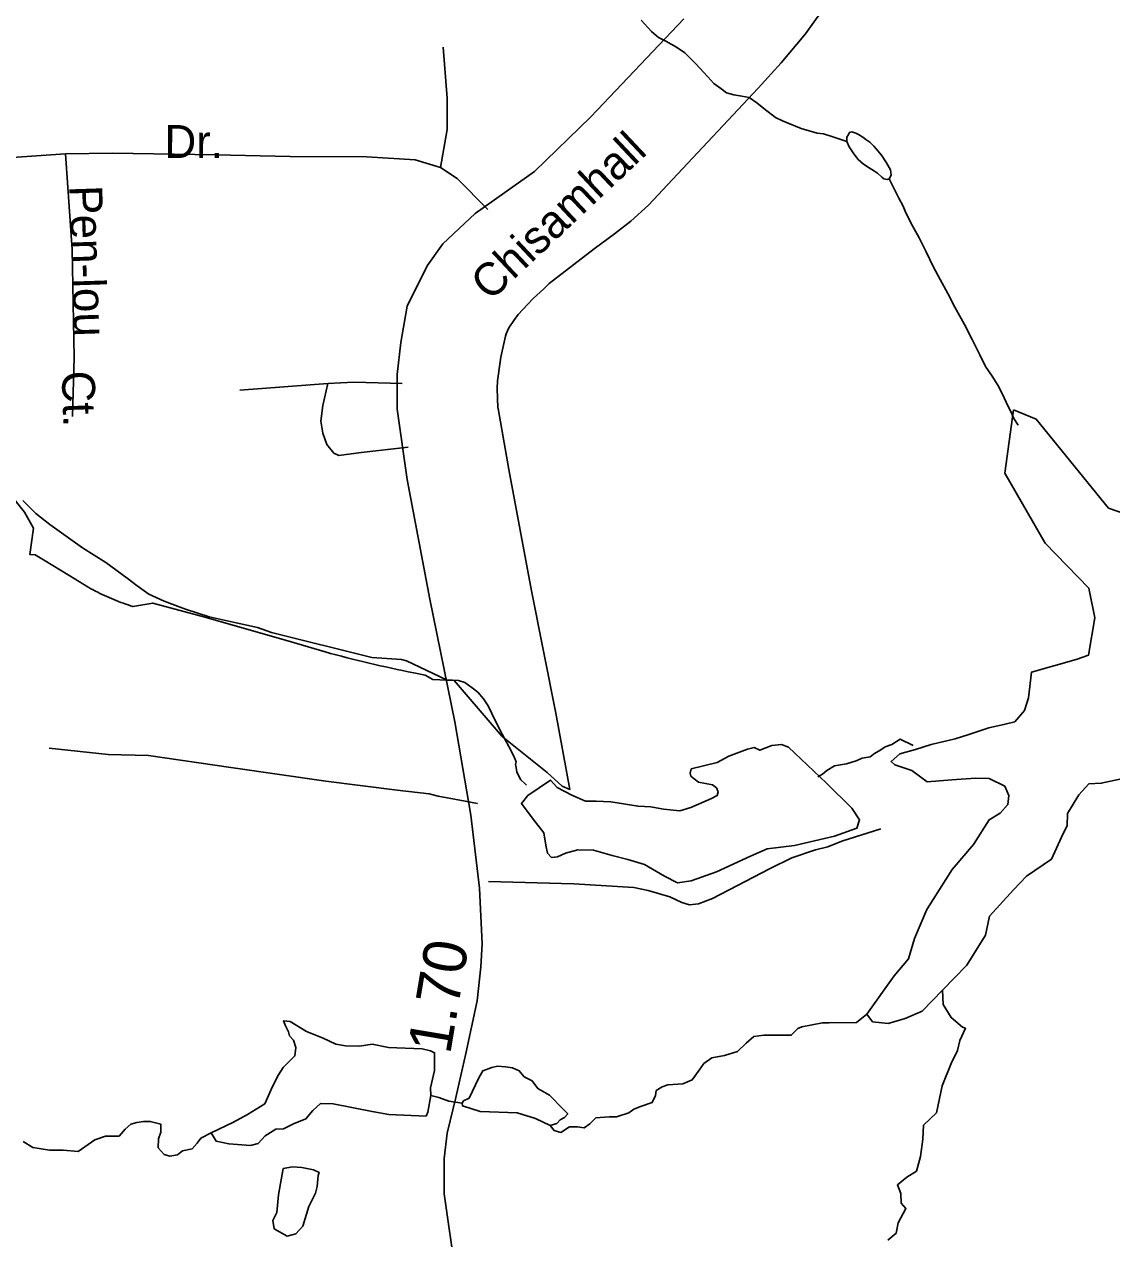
# Model space of a CAD drawing. Extents: x 2082433 to 2279600, y 546599 to 755198.
# Drawn here: x 2095833 to 2098975, y 639289 to 642798 of the extents above; entities that cross this region are included whole.
import ezdxf

# ---------------------------------------------------------------- set-up
doc = ezdxf.new("R2010")
doc.units = 0
for name, color, linetype in [('Exist Boundary Political Fire Districts', 7, 'Continuous'), ('Exist Hydrographic Creek Single Shore', 7, 'Continuous'), ('Exist Hydrographic Lake Shore', 7, 'Continuous'), ('Exist Hydrographic Pond Over 1500 Sq Ft', 7, 'Continuous'), ('Exist Road Non-System Type 51', 7, 'Continuous'), ('Exist Road Non-System Type 51 Label', 7, 'Continuous'), ('Exist Road Secondary Mileage Hundredths English Label', 7, 'Continuous'), ('Exist Road Secondary Type 51 Attributed', 7, 'Continuous'), ('Exist Road Secondary Type 51 Label', 7, 'Continuous')]:
    doc.layers.add(name, color=color, linetype=linetype)

msp = doc.modelspace()

# ---------------------------------------------------------------- linework, layer by layer
at = {"layer": 'Exist Boundary Political Fire Districts'}
for points in [[(2098155.5, 642861.7), (2098090.5, 642770.9), (2098020.5, 642686.3), (2097953.3, 642613.5), (2097706, 642349.4), (2097636.3, 642275.7), (2097586, 642229.6), (2097538.3, 642192.8), (2097480, 642149.7), (2097350, 642048.7), (2097335, 642034.9), (2097302.4, 642004.8), (2097260.4, 641959.8), (2097247.5, 641942.3), (2097232.9, 641921), (2097225.1, 641903.7), (2097223.7, 641897.2), (2097209.6, 641836.1), (2097200.7, 641768.2), (2097199.7, 641745.8), (2097201.6, 641689.9), (2097201.8, 641688.2), (2097232.7, 641511.5), (2097299, 641161.4), (2097369.3, 640807.7), (2097409.7, 640587.4), (2097387.5, 640596.3), (2097343.7, 640635.9), (2097214.1, 640740.5), (2097075.2, 640902.1), (2097013.7, 640904.7), (2096990.8, 640917.1), (2096958.4, 640924.3), (2096942.2, 640927.5), (2096926.2, 640930.8), (2096910, 640934.1), (2096894, 640937.6), (2096877.8, 640941.1), (2096861.6, 640944.6), (2096845.6, 640948.3), (2096829.6, 640952.1), (2096813.6, 640955.9), (2096797.4, 640959.7), (2096781.4, 640963.7), (2096765.6, 640967.7), (2096749.6, 640971.9), (2096733.6, 640976), (2096717.8, 640980.3), (2096701.8, 640984.6), (2096604, 641013.4), (2096358.6, 641083.8), (2096204, 641125.7), (2096146.8, 641115.7), (2096139.8, 641117.9), (2096132.8, 641120.2), (2096125.9, 641122.6), (2096119.1, 641125.1), (2096112.1, 641127.6), (2096105.3, 641130.2), (2096098.4, 641132.9), (2096091.6, 641135.6), (2096084.8, 641138.5), (2096078.1, 641141.4), (2096071.3, 641144.4), (2096064.7, 641147.4), (2096058.2, 641150.5), (2096051.4, 641153.7), (2096044.9, 641157), (2096038.3, 641160.4), (2096031.9, 641163.8), (2096025.4, 641167.3), (2096019, 641170.8), (2096012.7, 641174.4), (2096006.3, 641178.1), (2096000, 641181.9), (2095993.8, 641185.8), (2095987.4, 641189.7)], [(2095987.4, 641189.7), (2095981.3, 641193.6), (2095892.9, 641247.9), (2095864.6, 641265.2), (2095849, 641266), (2095859.3, 641342.1), (2095833.4, 641388.1), (2095809.9, 641417.3), (2095796.3, 641436.4), (2095719, 641489.7), (2095621.6, 641631.3), (2095543.7, 641668.5), (2095450, 641711.7), (2095302, 641847.1), (2095229.6, 641871.3), (2095175.4, 641897.6), (2095148, 641908), (2095048.9, 641984.4), (2095000.1, 642023.6), (2095005, 642083.8), (2092567, 642644)]]:
    msp.add_lwpolyline(points, dxfattribs=at)
at = {"layer": 'Exist Hydrographic Creek Single Shore'}
for points in [[(2097615.1, 642809.7), (2097645.1, 642777.6), (2097665.6, 642759.9), (2097687.1, 642749.7), (2097717.9, 642732.1), (2097741.5, 642715.9), (2097773.7, 642684.3), (2097807.7, 642646.3), (2097825.7, 642626.6), (2097845.8, 642612.5), (2097861.6, 642600.4), (2097883.6, 642594.6), (2097905.9, 642590.5), (2097927.8, 642586.7), (2097949.8, 642570.8), (2097969.7, 642554.8), (2098004.1, 642529), (2098024, 642519), (2098078.2, 642497), (2098123.9, 642483.2), (2098142.3, 642481.2), (2098166.1, 642473.6), (2098210.2, 642459.6)], [(2098332.4, 642351.9), (2098338.4, 642361.9), (2098336.3, 642378), (2098324.4, 642398.1), (2098310.3, 642420.1), (2098294.5, 642437.9), (2098288.1, 642445.8), (2098276, 642457.8), (2098264.3, 642465.6), (2098256.3, 642471.7), (2098244, 642479.6), (2098236.2, 642483.6), (2098224.1, 642487.5), (2098217.8, 642485.6), (2098214.3, 642479.7), (2098210, 642471.8), (2098210.2, 642459.6)], [(2098210.2, 642459.6), (2098216.4, 642443.7), (2098230.5, 642423.7), (2098242.2, 642407.7), (2098258.2, 642393.9), (2098274.4, 642383.8), (2098290.2, 642374.1), (2098298.6, 642367.9), (2098310.7, 642356), (2098316.6, 642351.8), (2098326.7, 642349.9), (2098332.4, 642351.9)], [(2098332.4, 642351.9), (2098360.5, 642296.1), (2098372.8, 642272.3), (2098378.8, 642258), (2098395, 642224.4), (2098419.2, 642180.6), (2098439, 642140.2), (2098459.3, 642098.6), (2098479.4, 642060.7), (2098501.6, 642020.4), (2098521.5, 641981), (2098549.6, 641930.9), (2098572.1, 641886.9), (2098594.1, 641843), (2098610.1, 641809), (2098630.2, 641781.2), (2098646.6, 641755.1), (2098660.1, 641729.2), (2098674.9, 641695.3), (2098684.5, 641677.2), (2098692.7, 641659.4), (2098704.6, 641639.3)], [(2095828.3, 641422.3), (2095866.1, 641384.5), (2095906.2, 641352.5), (2095954.2, 641318.9), (2096000.6, 641285.1), (2096068.2, 641243.2), (2096130.4, 641197.3), (2096158.7, 641175.6), (2096192.9, 641151.7), (2096236.8, 641131.7), (2096299.1, 641108.1), (2096366.8, 641086.1), (2096445.1, 641068.5), (2096507, 641054.7), (2096547.2, 641040.9), (2096837, 640968.9), (2096923.2, 640962.4), (2096936.9, 640958.6), (2097053.1, 640904.2), (2097087.3, 640902.3), (2097105.4, 640896.7), (2097127.5, 640880.8), (2097143.3, 640868.7), (2097159.5, 640848.8), (2097173.7, 640828.8), (2097183.7, 640807), (2097197.7, 640778.9), (2097214.1, 640746.9), (2097240.1, 640699.1), (2097249.7, 640679), (2097254.3, 640666.9), (2097252, 640659.2), (2097254, 640651.1), (2097256.1, 640637.1), (2097268, 640615), (2097280.1, 640603.4), (2097284.2, 640599.2)], [(2098125.9, 640623.8), (2098139.7, 640631.8), (2098151.6, 640642.2), (2098173.9, 640655.9), (2098209.3, 640661), (2098236.4, 640669.8), (2098254.2, 640677.6), (2098277, 640681), (2098289.3, 640690.8), (2098307.7, 640702), (2098320.5, 640710.7), (2098340, 640717.4), (2098363.6, 640732.6), (2098401.9, 640714.3)], [(2098327.9, 639284.8), (2098352.1, 639305.1), (2098357.9, 639334.8), (2098380.4, 639376.8), (2098367.1, 639392.2), (2098366.1, 639419.8), (2098355.8, 639444.4), (2098383.5, 639466.9), (2098411.2, 639484.4), (2098422.4, 639526.4), (2098429.9, 639577), (2098431.6, 639617), (2098468.5, 639652.4), (2098484.9, 639731.3), (2098511.6, 639795.8), (2098530, 639832.7), (2098536.2, 639861.4), (2098552.6, 639897.3), (2098544.4, 639900.3), (2098511.6, 639928), (2098488, 639965.9), (2098486, 640006.9)], [(2097352.3, 639616.5), (2097363.6, 639602.2), (2097383.1, 639596), (2097408.7, 639612.4), (2097431.2, 639612.4), (2097450.7, 639609.4), (2097467.1, 639620.6), (2097484.5, 639638), (2097523.4, 639641.1), (2097543.9, 639641.1), (2097579.8, 639652.4), (2097594.1, 639663.7), (2097616.6, 639671.9), (2097647.4, 639683.1), (2097656.6, 639702.6), (2097658.7, 639716.9), (2097676.1, 639728.2), (2097692.5, 639733.3), (2097735.5, 639736.4), (2097763.2, 639747.7), (2097782.6, 639776.4), (2097797, 639795.8), (2097819.5, 639812.2), (2097856.4, 639818.4), (2097894.3, 639829.6), (2097918.9, 639854.2), (2097941.4, 639873.7), (2097970.1, 639876.8), (2097986.5, 639876.8), (2098049, 639876.8), (2098068.5, 639896.2), (2098079.7, 639901.3), (2098139.2, 639912.6), (2098158.6, 639912.6), (2098237.5, 639913.6), (2098268, 639938.3)], [(2097008.1, 639702.6), (2097030.6, 639697.5), (2097059.3, 639686.2), (2097098.2, 639681.1)], [(2095829.9, 639570.4), (2095857.5, 639553), (2095905.7, 639544.8), (2095945.6, 639544.8), (2095988.7, 639540.7), (2096036.8, 639574.5), (2096067.6, 639585.8), (2096106.5, 639585.8), (2096123.9, 639605.3), (2096140.3, 639619.6), (2096157.7, 639624.7), (2096177.2, 639627.8), (2096196.6, 639627.8), (2096227.4, 639619.6), (2096227.4, 639597.1), (2096220.2, 639577.6), (2096219.2, 639552), (2096236.6, 639532.5), (2096253, 639527.4), (2096275.5, 639531.5), (2096289.9, 639542.8), (2096317.5, 639548.9), (2096331.9, 639565.3), (2096343.1, 639579.6), (2096372.9, 639595)]]:
    msp.add_lwpolyline(points, dxfattribs=at)
at = {"layer": 'Exist Hydrographic Lake Shore'}
for points in [[(2098268, 639938.3), (2098346.6, 640048.9), (2098387.6, 640098.1), (2098405, 640156.5), (2098440.9, 640240.5), (2098514.6, 640356.2), (2098576.1, 640428), (2098621.2, 640499.7), (2098653, 640519.1), (2098675.5, 640543.7), (2098677.5, 640569.3), (2098666.3, 640597), (2098620.7, 640619), (2098581.8, 640620.1), (2098513.6, 640614.9), (2098441.9, 640609.3), (2098397.9, 640641.6), (2098348.7, 640658.5), (2098337.9, 640668.2), (2098362.5, 640690.2), (2098408.1, 640702.5), (2098453.2, 640716.9), (2098522.8, 640733.3), (2098562.8, 640745.6), (2098620.2, 640765), (2098667.3, 640776.3), (2098695, 640782.4), (2098723.7, 640815.2), (2098734.9, 640852.1), (2098743.1, 640925.7), (2098872.7, 640962.8), (2098908.1, 640975.1), (2098926.2, 641082.7), (2098909.2, 641168.4), (2098783.1, 641298.8), (2098666.2, 641501.4), (2098691.2, 641684.5)], [(2099568.2, 640869.6), (2099634.5, 640993.5), (2099637.5, 641018.1), (2099642.7, 641043.7), (2099638.6, 641061.1), (2099621.1, 641077.5), (2099598.6, 641083.7), (2099592.5, 641097), (2099576.1, 641097), (2099548.4, 641072.4), (2099516.6, 641047.8), (2099488, 641049.9), (2099432.6, 641074.4), (2099381.4, 641097), (2099339.4, 641119.5), (2099299.4, 641156.4), (2099158.1, 641333.9), (2098966.2, 641400.1), (2098757.3, 641657), (2098691.2, 641684.5)], [(2098268, 639938.3), (2098284.1, 639915.7), (2098329.2, 639910.6), (2098378.4, 639924.9), (2098427.6, 639946.4), (2098486, 640006.9), (2098556.7, 640079.6), (2098611, 640165.7), (2098622.2, 640221), (2098691.9, 640296.8), (2098728.8, 640336.8), (2098801.5, 640386), (2098835.3, 640459.7), (2098846.6, 640482.3), (2098847.6, 640518.1), (2098880.4, 640571.4), (2098909.1, 640603.2), (2098945, 640605.2), (2099016.7, 640620.6)]]:
    msp.add_lwpolyline(points, dxfattribs=at)
at = {"layer": 'Exist Hydrographic Pond Over 1500 Sq Ft'}
for points in [[(2097760.1, 640647.2), (2097834.9, 640664.6), (2097868.7, 640683.1), (2097923, 640703.6), (2097942.4, 640708.7), (2097958.8, 640700.5), (2097992.6, 640713.8), (2098021.3, 640716.9), (2098040.8, 640709.7), (2098077.7, 640674.9), (2098151.5, 640605.2), (2098224.2, 640533.5), (2098246.7, 640499.7), (2098238.5, 640475.1), (2098174, 640452.5), (2098058.2, 640424.9), (2097979.3, 640415.7), (2097931.2, 640394.2), (2097832.8, 640349.1), (2097760.1, 640323.5), (2097720.1, 640317.3), (2097683.2, 640336.8), (2097624.8, 640370.6), (2097576.7, 640384.9), (2097531.6, 640396.2), (2097477.3, 640411.6), (2097432.2, 640412.6), (2097396.4, 640403.4), (2097373.8, 640392.1), (2097356.4, 640390.1), (2097345.1, 640403.4), (2097340, 640425.9), (2097333.9, 640461.8), (2097303.1, 640501.7), (2097269.3, 640546.8), (2097287.8, 640569.3), (2097353.3, 640614.4), (2097372.8, 640592.9), (2097414.8, 640570.4), (2097454.8, 640553), (2097485.5, 640553), (2097527.5, 640551.9), (2097606.4, 640538.6), (2097643.3, 640536.6), (2097680.2, 640530.4), (2097727.3, 640525.3), (2097759.1, 640535.5), (2097818.5, 640561.1), (2097834.9, 640569.3), (2097837.9, 640580.6), (2097832.8, 640591.9), (2097821.6, 640600.1), (2097781.6, 640608.3), (2097768.3, 640617.5), (2097759.1, 640625.7), (2097757, 640633.9)], [(2096372.9, 639595), (2096437.4, 639625.8), (2096477.4, 639648.3), (2096527.6, 639679), (2096550.1, 639729.2), (2096567.5, 639763), (2096580.8, 639783.5), (2096603.4, 639806.1), (2096614.7, 639817.3), (2096617.7, 639841.9), (2096610.6, 639862.4), (2096599.3, 639875.7), (2096596.2, 639887), (2096588, 639904.4), (2096581.9, 639918.8), (2096601.3, 639916.7), (2096648.5, 639888), (2096696.6, 639868.6), (2096733.5, 639851.1), (2096761.2, 639846), (2096801.1, 639845), (2096838, 639851.1), (2096885.1, 639841.9), (2096982.5, 639837.8), (2097007, 639831.7), (2097018.3, 639826.6), (2097018.3, 639775.3), (2097007, 639725.1), (2097008.1, 639702.6), (2096998.9, 639654.4), (2096993.7, 639643.2), (2096886.2, 639648.3), (2096838, 639656.5), (2096725.3, 639679), (2096688.4, 639680.1), (2096666.9, 639659.6), (2096646.4, 639635), (2096610.6, 639620.6), (2096581.9, 639606.3), (2096559.3, 639605.3), (2096528.6, 639586.8), (2096509.1, 639564.3), (2096486.6, 639558.1), (2096424.1, 639563.3), (2096387.2, 639571.4)], [(2097146.4, 639753.8), (2097118.7, 639695.4), (2097102.3, 639687.2), (2097098.2, 639681.1), (2097099.3, 639672.9), (2097150.5, 639656.5), (2097257, 639652.4), (2097310.3, 639636), (2097352.3, 639616.5), (2097371.8, 639621.7), (2097381, 639632.9), (2097394.3, 639639.1), (2097403.5, 639650.3), (2097390.2, 639663.7), (2097350.3, 639703.6), (2097316.5, 639723.1), (2097300.1, 639745.6), (2097277.5, 639756.9), (2097263.2, 639774.3), (2097243.7, 639782.5), (2097223.2, 639785.6), (2097200.7, 639787.6), (2097184.3, 639783.5), (2097157.7, 639774.3)], [(2096580.8, 639491.5), (2096567.5, 639415.7), (2096562.4, 639364.5), (2096551.1, 639342), (2096555.2, 639317.4), (2096592.1, 639296.9), (2096617.7, 639303), (2096638.2, 639325.6), (2096654.6, 639381.9), (2096674.1, 639420.8), (2096679.2, 639440.3), (2096682.3, 639472.1), (2096685.3, 639480.3), (2096669, 639488.5), (2096635.1, 639494.6), (2096607.5, 639496.7)]]:
    msp.add_lwpolyline(points, close=True, dxfattribs=at)
at = {"layer": 'Exist Road Non-System Type 51'}
msp.add_line((2096709.7, 641759.8), (2096455.8, 641741), dxfattribs=at)
for points in [[(2097035.7, 642384.4), (2097054.5, 642494), (2097054.5, 642584.9), (2097042.9, 642732.1)], [(2095952.3, 642423.4), (2095797.9, 642413.3), (2095551.2, 642398.8)], [(2097035.7, 642384.4), (2096962.1, 642406), (2096822.2, 642414.7), (2096601.5, 642416.1), (2096385.1, 642421.2), (2096087.9, 642425.5), (2095952.3, 642423.4)], [(2095952.3, 642423.4), (2095971, 642147.8), (2095976.8, 641835.5), (2095972.5, 641664.5)], [(2097172.7, 642263.2), (2097083.3, 642352.7), (2097035.7, 642384.4)], [(2096924.6, 641760.5), (2096784.7, 641764.1), (2096709.7, 641759.8)], [(2096709.7, 641759.8), (2096695.2, 641696.3), (2096689.5, 641651.6), (2096695.2, 641616.9), (2096706.8, 641583.8), (2096727, 641559.2), (2096741.4, 641552), (2096806.3, 641560.7), (2096941.9, 641576.5)], [(2097142.5, 640546.5), (2097076.1, 640558.8), (2097028.5, 640567.4), (2097002.5, 640574.6), (2096910.2, 640584.7), (2096703.9, 640610.7), (2096429.8, 640651.1), (2096191.8, 640685), (2096074.9, 640687.9), (2095904.7, 640706.6)], [(2097174.2, 640321.5), (2097420.9, 640314.2), (2097594, 640304.1), (2097635.8, 640295.5), (2097697.9, 640276.7), (2097732.5, 640260.9), (2097755.6, 640253.7), (2097781.5, 640256.5), (2097821.9, 640272.4), (2097987.8, 640359), (2098051.3, 640390), (2098119.1, 640413.1), (2098155.2, 640421.7), (2098195.6, 640437.6), (2098308.1, 640473.7)]]:
    msp.add_lwpolyline(points, dxfattribs=at)
at = {"layer": 'Exist Road Secondary Type 51 Attributed'}
msp.add_lwpolyline([(2097079.8, 639184.2), (2097046, 639418.8), (2097046, 639521.2), (2097055.2, 639594), (2097079.8, 639697.5), (2097108.5, 639824.5), (2097141.3, 639976.1), (2097152.5, 640074.5), (2097155.6, 640141.1), (2097148.4, 640301.9), (2097122.8, 640513), (2097076.7, 640782.4), (2097005, 641136.9), (2096939.4, 641483.2), (2096910.7, 641686.1), (2096910.7, 641786.5), (2096921, 641878.7), (2096939.4, 641983.2), (2096996.8, 642100), (2097041.9, 642163.5), (2097136.1, 642251.6), (2097306.9, 642372.9), (2097470.1, 642530.3), (2097738.3, 642814.3)], dxfattribs=at)

# ---------------------------------------------------------------- texts
at = {"layer": 'Exist Road Non-System Type 51 Label'}
for s, rotation, p in [('Dr.', 359.8168, (2096237.7, 642412)), ('Pen-lou', 271.8765, (2095962.7, 642331.5)), ('Ct.', 271.8765, (2095940.8, 641795.6))]:
    msp.add_text(s, height=95, rotation=rotation, dxfattribs=at).set_placement(p)
at = {"layer": 'Exist Road Secondary Mileage Hundredths English Label'}
msp.add_text('1.70', height=125, rotation=80.4401, dxfattribs=at).set_placement((2097063.3, 639819.3))
at = {"layer": 'Exist Road Secondary Type 51 Label'}
msp.add_text('Chisamhall', height=95, rotation=43.2424, dxfattribs=at).set_placement((2097178.8, 641995.4))

doc.saveas('drawing.dxf')
